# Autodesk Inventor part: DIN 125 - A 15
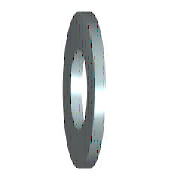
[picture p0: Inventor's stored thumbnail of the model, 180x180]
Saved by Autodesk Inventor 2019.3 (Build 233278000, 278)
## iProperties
Created: 2018-01
Part Number: DIN 125 - A 15
Material: Ocel, měkká
Description: Podložka
Document SubType Name: Modeling
Standard: DIN 125
Designer: B-hon
Standards Organization: DIN
Language: cs-CZ
Size Designation: A 15
Categories: <MemberInstance><Categories><Category DisplayName="Spojovací materiál" InternalName="e4da775c-781d-43d5-af7c-5136215cf5a6" Mnemonic="FSTN"><Category DisplayName
Density: 7.85 g/cm^3
Appearance: Pololeštěná
IsCustomPart: 0
Author: B-hon
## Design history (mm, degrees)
sketch "Náčrt"
  geometry: C1 r 14 at (0, 0); C2 r 7.5 at (0, 0); 1 further point
  constraints: 2 centre point, 2 coincident
  dimensions: "d0" = 15 diameter of C2 (= SD1); "d1" = 28 diameter of C1 (= SD2)
extrude "Těleso" new body sketch "Náčrt" distance "d2" = 2.5 (= SD); taper "d3" = 0 deg
workaxis "Work Axis1"
workplane "Work Plane1"
body "Solid1"
other parameters: "SD1" = 15 [user parameter; used in 1 equation term], "SD2" = 28 [user parameter; used in 1 equation term], "SD" = 2.5 [user parameter; used in 1 equation term], "d4" = 0, "d5" = 0, "d6" = 0, "d7" = 0, "NND" = 14 [user parameter]
